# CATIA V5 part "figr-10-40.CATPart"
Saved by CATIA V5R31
Part number: Part3
Bounding box of the stored display mesh (mm): x -57.458 to 20, y -85.932 to 127.979, z -59.826 to 86.386
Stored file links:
  D:\PROJECTS\Project 2021\US EDITION\CATIA V5 6R 2021\Resources\Part Files\c10_catia_v5_6r2021_prt\c10_catia_v5_6r2021_prt\figr-10-40.CATPart
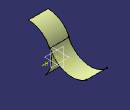
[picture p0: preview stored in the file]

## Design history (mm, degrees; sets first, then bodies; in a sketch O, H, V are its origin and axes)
Body1 (main body)
  Sketch1 on yz-plane, origin (0, 0, 0), H (0, 1, 0), V (0, 0, 1)
    arc A1 centre (-86.3872, 0) radius 86.3872 from (-24.0683, -59.8256) to (-85.9323, 86.386) ccw
    point P1 (-86.3872, 0)
    coincidence: A1 O, P1 H
  Extrude1: Element1 Sketch1, Lim1 20, Lim2 53
  Sketch2 on zx-plane, origin (0, 0, 0), H (-1, 0, 0), V (0, 0, 1)
    line L1 (-18.8028, 37.5161) -> (51.5353, 37.5161)
    horizontal: L1 H
  Project1: ToProject Sketch2, Support Extrude1
  Sketch3 on xy-plane, origin (0, 0, 0), H (1, 0, 0), V (0, 1, 0)
    line L1 (-57.4576, 127.9794) -> (17.5097, 127.9794)
    horizontal: L1 H
  Sweep1: type Circle, Guide (Project1; Sketch3), Reference Extrude1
